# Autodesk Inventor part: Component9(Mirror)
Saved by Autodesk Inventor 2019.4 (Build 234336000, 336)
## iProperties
Created: 2020-06
Part Number: Component9(Mirror)
Material: Generic
Document SubType Name: Modeling
Designer: Administrator
Density: 1 g/cm^3
Appearance: Default
Title: Component9(Mirror)
Author: Administrator
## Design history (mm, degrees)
